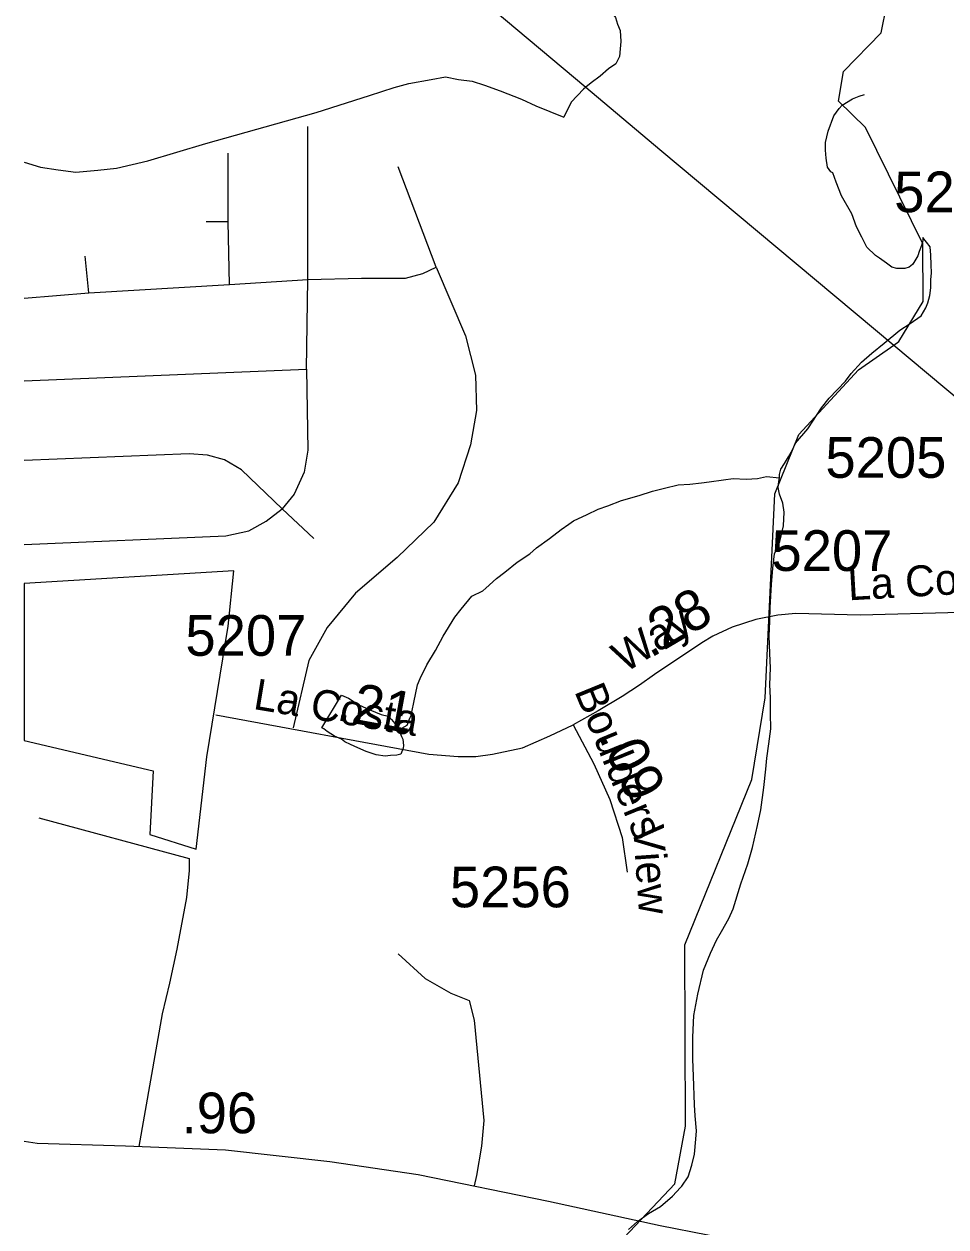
# Model space of a CAD drawing. Extents: x 2169602 to 2449496, y 721995 to 810662.
# Drawn here: x 2379098 to 2381932, y 782129 to 785825 of the extents above; entities that cross this region are included whole.
import ezdxf

# ---------------------------------------------------------------- set-up
doc = ezdxf.new("R2010")
doc.units = 0
doc.layers.add('Default', color=7, linetype='Continuous')

msp = doc.modelspace()

# ---------------------------------------------------------------- linework, layer by layer
at = {"layer": 'Default'}
for p, q in [((2379098.1, 784105.8), (2379098.1, 783623.3)), ((2379098.1, 784105.8), (2379098.1, 783623.3)), ((2379143.6, 783385.9), (2379605.3, 783261.3))]:
    msp.add_line(p, q, dxfattribs=at)
for points in [[(2379692.8, 786578.9), (2380014.5, 786310.7), (2380824.6, 785630.5)], [(2380628.2, 786152), (2380689.4, 786101.8), (2380767.5, 786022.2), (2380829.9, 785952.3), (2380888.2, 785890.7), (2380904.3, 785862.8), (2380916.3, 785844.8), (2380922.5, 785824.8), (2380930.5, 785804.9), (2380932.6, 785770.8), (2380930.7, 785748.9), (2380928.9, 785724.9), (2380917, 785702.8), (2380895.1, 785686.8), (2380869.2, 785664.8), (2380841.2, 785644.5), (2380824.6, 785630.5)], [(2381771.6, 784838.2), (2381787.2, 784849), (2381862.2, 784972.1), (2381861.2, 785149.2), (2381685.1, 785507.2), (2381601.2, 785587.6), (2381617.2, 785679.1), (2381733.3, 785798.1), (2381750.2, 785884.1)], [(2379098.1, 785400), (2379148.9, 785385.3), (2379202.9, 785377.4), (2379256.9, 785369.7), (2379324.9, 785375.9), (2379382.8, 785382.3), (2379478.6, 785404.6), (2379656.5, 785457.3), (2379995.8, 785552.8), (2380159.7, 785605.6), (2380235.6, 785629.9), (2380281.4, 785642.2), (2380349.3, 785654.4), (2380393.2, 785662.7), (2380433.3, 785654.9), (2380475.3, 785649), (2380513.3, 785637.2), (2380561.5, 785619.2), (2380627.6, 785593.7), (2380671.6, 785573.8), (2380757.7, 785538.2)], [(2380824.6, 785630.5), (2380817.4, 785624.4), (2380779.6, 785584.4), (2380757.7, 785538.2)], [(2380824.6, 785630.5), (2381052, 785439.4), (2381771.6, 784838.2)], [(2381861, 785168.5), (2381861, 785158.3), (2381856.9, 785144.3), (2381849.3, 785126.4), (2381845.2, 785112.4), (2381838.9, 785102.4), (2381832.9, 785092.4), (2381829.4, 785086.5), (2381819.2, 785078.2), (2381805.2, 785074.2), (2381781.4, 785074.2), (2381765.7, 785078.2), (2381748.8, 785090.1), (2381727.3, 785105.9), (2381715, 785113.9), (2381689.2, 785139.7), (2381673, 785169.8), (2381656.6, 785201.4), (2381642.8, 785241.6), (2381610.4, 785297.2), (2381594, 785339.4), (2381584.2, 785367.3), (2381578, 785371.1), (2381568.2, 785385.2), (2381563.9, 785413), (2381561.8, 785437.2), (2381561.6, 785461.2), (2381569.8, 785495.2), (2381587.7, 785543.3), (2381603.3, 785565.2), (2381612.9, 785575.5), (2381645.1, 785595.4), (2381665.2, 785603.3), (2381681.9, 785608.6)], [(2379970.1, 785040), (2379970.1, 785510.4)], [(2379725.6, 785216.9), (2379725.6, 785427.6)], [(2380365, 785077.6), (2380248.4, 785386.2)], [(2379725.6, 785216.9), (2379657.9, 785216.9)], [(2379729.4, 785024.9), (2379725.6, 785216.9)], [(2381622.9, 784727.5), (2381640.6, 784751.5), (2381672.6, 784785.6), (2381704.1, 784814.1), (2381742.3, 784844.1), (2381790.3, 784884.3), (2381821.6, 784904.3), (2381855.9, 784928.7), (2381869.6, 784952.6), (2381875.8, 784968.7), (2381881.9, 784990.5), (2381885.4, 785014.7), (2381885.2, 785038.6), (2381887.7, 785060.6), (2381886.8, 785084.6), (2381885.2, 785114.5), (2381883.1, 785140.4), (2381861, 785168.5)], [(2379296.9, 784998.6), (2379285.6, 785111.5)], [(2380365, 785077.6), (2380455.3, 784866.8), (2380485.4, 784746.4), (2380489.1, 784637.3), (2380470.3, 784531.9), (2380432.7, 784415.2), (2380357.5, 784294.8), (2380244.7, 784185.7), (2380116.8, 784076.5), (2380030.3, 783971.1), (2379973.9, 783869.5), (2379925, 783662.5)], [(2379970.1, 785040), (2380135.6, 785043.7), (2380271, 785043.7), (2380323.6, 785058.8), (2380365, 785077.6)], [(2379296.9, 784998.6), (2379729.4, 785024.9)], [(2379729.4, 785024.9), (2379970.1, 785040)], [(2379966.4, 784764.1), (2379970.1, 785040)], [(2379098.1, 784982.4), (2379296.9, 784998.6)], [(2379098.1, 778310.7), (2379173, 778679.4), (2379219.1, 779770.8), (2379325.1, 780155.8), (2379449.2, 780415.7), (2379706.1, 780781.1), (2380021.1, 781056.8), (2380171.2, 781148.8), (2380269.2, 781524.1), (2380410.1, 781734.5), (2380784.1, 781861.3), (2380925.1, 782078.2), (2381099, 782261.7), (2381131, 782438.2), (2381129.2, 782995.8), (2381335, 783503.4), (2381376.1, 783755.1), (2381406.2, 784381.1), (2381480.2, 784563.3), (2381663.1, 784762.9), (2381771.6, 784838.2)], [(2381771.6, 784838.2), (2382292.3, 784403.3), (2382758.2, 784008.7)], [(2379098.1, 784728.9), (2379966.4, 784764.1)], [(2379966.4, 784764.1), (2379970.1, 784515.7), (2379958.8, 784448), (2379928.7, 784380.2), (2379891.1, 784335.1)], [(2381420.1, 784430.8), (2381420.1, 784440.9), (2381424, 784457), (2381436.1, 784475), (2381447.8, 784494.8), (2381459.9, 784516.9), (2381469.8, 784536.9), (2381507.3, 784581.1), (2381548.9, 784645.3), (2381573.1, 784675.4), (2381622.9, 784727.5)], [(2379891.1, 784335.1), (2379767, 784455.5), (2379714.4, 784485.6), (2379661.7, 784500.7), (2379605.3, 784504.4), (2379098.1, 784483.6)], [(2380249.9, 783655.9), (2380275.9, 783670.2), (2380283.5, 783692.1), (2380287.8, 783700), (2380291.3, 783716.1), (2380295.8, 783740.2), (2380307.3, 783794.4), (2380315.3, 783814.3), (2380336.6, 783856.1), (2380362.9, 783900.4), (2380386.7, 783944.6), (2380422.4, 784002.5), (2380442, 784026.7), (2380474.2, 784066.9), (2380508.1, 784082.9), (2380517.9, 784091.1), (2380550.1, 784121.1), (2380575.9, 784141.2), (2380613.7, 784171.5), (2380653.2, 784197.5), (2380673.3, 784215.6), (2380713.3, 784243.7), (2380749.4, 784271.9), (2380773, 784288.2), (2380786.9, 784298.2), (2380829, 784318.2), (2380862.6, 784334.6), (2380892.3, 784344.7), (2380934.6, 784360.7), (2380988.7, 784376.8), (2381030.3, 784389.2), (2381066.4, 784399.1), (2381108.5, 784409.4), (2381144.5, 784411.6), (2381180.4, 784415.5), (2381204.2, 784418), (2381248.1, 784424), (2381278.2, 784428.3), (2381318.2, 784426.3), (2381352.3, 784428.5), (2381379.9, 784434.8), (2381420.1, 784430.8)], [(2380956.5, 782121.6), (2380984.2, 782145.7), (2381018, 782169.8), (2381054.1, 782192), (2381091.6, 782224), (2381115.6, 782250), (2381119.7, 782254.2), (2381139.6, 782282.5), (2381151.1, 782318.5), (2381159.3, 782352.5), (2381162.8, 782398.2), (2381165.1, 782424.3), (2381160.7, 782470.3), (2381158.7, 782504.3), (2381156, 782592.3), (2381154, 782644.1), (2381153.8, 782652.3), (2381153.6, 782712.4), (2381157.3, 782778.3), (2381169.2, 782844.3), (2381187, 782918.2), (2381208.3, 782970.2), (2381226.6, 783010.4), (2381242.4, 783036.4), (2381264.3, 783076.5), (2381277.8, 783106.5), (2381301.6, 783182.8), (2381323.4, 783244.8), (2381337.1, 783294.6), (2381352.9, 783362.8), (2381362.5, 783410.9), (2381372.6, 783478.7), (2381378.1, 783535.1), (2381381.6, 783569), (2381387.7, 783613.1), (2381393.7, 783658.9), (2381393.1, 783706.8), (2381393.1, 783755), (2381390.8, 783794.8), (2381392.7, 783846.8), (2381390.6, 783890.9), (2381388.6, 783944.8), (2381390.4, 783988.7), (2381391.6, 784032.7), (2381395.7, 784102.7), (2381399.4, 784152.8), (2381405, 784197), (2381421.2, 784234.7), (2381432.9, 784282.9), (2381434.9, 784324.7), (2381430.6, 784353), (2381420.3, 784380.9), (2381416.4, 784400.9), (2381418.3, 784418.9), (2381420.1, 784430.8)], [(2379098.1, 784225.3), (2379718.1, 784252.3), (2379789.6, 784267.3), (2379842.2, 784297.4), (2379891.1, 784335.1)], [(2379891.1, 784335.1), (2379988.9, 784244.7)], [(2379098.1, 783623.3), (2379494.7, 783530.6), (2379484.7, 783334.9), (2379627.7, 783289.8), (2379660.4, 783573.3), (2379725.7, 783974.6), (2379743.2, 784145.3), (2379098.1, 784105.8)], [(2379098.1, 783623.3), (2379494.7, 783530.6), (2379484.7, 783334.9), (2379627.7, 783289.8), (2379660.4, 783573.3), (2379725.7, 783974.6), (2379743.2, 784145.3), (2379098.1, 784105.8)], [(2382198, 784029.7), (2382110, 784022.3), (2381976.9, 784016.5), (2381668.5, 784009.1), (2381470.2, 784013.5), (2381414.7, 784008.3), (2381347.9, 783995.4), (2381274.6, 783971.7), (2381215.4, 783944.6), (2381181.8, 783923.3), (2381036.2, 783826.3), (2380989.8, 783793.3), (2380936.6, 783758.3), (2380863.1, 783714.8), (2380786, 783672.1)], [(2380249.9, 783655.9), (2380253.8, 783646), (2380257.9, 783636), (2380262.2, 783628), (2380264.1, 783608.3), (2380263.9, 783600.2), (2380256.3, 783581.9), (2380244.2, 783578), (2380224.1, 783577.8), (2380208.1, 783575.8), (2380180.2, 783579.6), (2380150, 783589.4), (2380124.4, 783601.4), (2380102.1, 783611.3), (2380084.4, 783619.3), (2380074.2, 783627.2), (2380052, 783637.1), (2380029.7, 783651), (2380020, 783659), (2380013.9, 783662.8), (2380073.6, 783763.2), (2380095.7, 783753.4), (2380127.7, 783733.6), (2380161.5, 783717.5), (2380195.8, 783703.8), (2380217.7, 783698), (2380228, 783687.9), (2380237.8, 783675.9), (2380246, 783665.7), (2380249.9, 783655.9)], [(2379687.3, 783702.1), (2380342.2, 783581.8), (2380432.5, 783574.3), (2380487, 783574.5), (2380537.8, 783581.8), (2380630.4, 783601.4), (2380714.2, 783638.2), (2380786, 783672.1)], [(2380786, 783672.1), (2380850, 783551.7), (2380898.8, 783442.5), (2380936.5, 783325.9), (2380952.1, 783218.8)], [(2379605.3, 783261.3), (2379605.3, 783223.7), (2379597.8, 783140.9), (2379567.7, 782982.8), (2379545.1, 782877.5), (2379522.6, 782783.4), (2379450.8, 782376.5)], [(2380248.4, 782967.8), (2380331.2, 782892.5), (2380410.1, 782847.4), (2380466.6, 782824.8), (2380481.6, 782764.6), (2380511.7, 782456), (2380504.2, 782376.9), (2380489.1, 782286.6), (2380482, 782255.1)], [(2379098.1, 782392.2), (2379138.8, 782386.5), (2379409.8, 782378.1), (2379717.5, 782365.6), (2380037.7, 782330), (2380309.7, 782290.2), (2380710.5, 782208.5), (2381053.7, 782133.1), (2381493.2, 782047.2), (2382389.9, 781877.6), (2382714.3, 781823.2), (2382917.8, 781787.6)]]:
    msp.add_lwpolyline(points, dxfattribs=at)

# ---------------------------------------------------------------- texts
for s, p in [('5208', (2381772.9, 785246.7)), ('5205', (2381561.4, 784430.6)), ('5207', (2381395.5, 784144.5)), ('5207', (2379594.1, 783883.8)), ('5256', (2380407.2, 783111.1)), ('.96', (2379582.5, 782416.8))]:
    msp.add_text(s, height=125, dxfattribs=at).set_placement(p)
for s, height, rotation, p in [('La Costa  ', 95, 3.2719, (2381632.8, 784054)), ('.28', 125, 30.6071, (2381023.7, 783875.4)), ('Way', 95, 32.2549, (2380945, 783829.5)), ('La Costa  ', 95, 350.4764, (2379799.9, 783720.9)), ('Boulders', 95, 292.2522, (2380788.8, 783775.5)), ('.21', 125, 349.593, (2380055.1, 783686.8)), ('.09', 125, 295.1999, (2380862.5, 783636)), ('View', 95, 273.9665, (2380969.7, 783361.9))]:
    msp.add_text(s, height=height, rotation=rotation, dxfattribs=at).set_placement(p)

doc.saveas('drawing.dxf')
